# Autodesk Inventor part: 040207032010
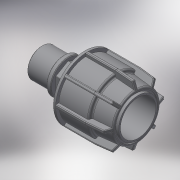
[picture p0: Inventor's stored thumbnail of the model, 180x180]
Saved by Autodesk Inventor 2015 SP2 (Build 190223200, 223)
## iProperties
Created: 2017-08
Part Number: 040207032010
Material: Generic
Description: PLASSON IRRIFIT ADAPTOR 32-1"M
Document SubType Name: Modeling
Designer: KIM
Density: 1 g/cm^3
Appearance: Default
Author: KIM
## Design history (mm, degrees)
derived "040207.ipt"
feature "Solid1::040207.ipt"
tag "TaggingFeature1"
body "Solid1"
other parameters: "d5" = 48, "d6" = 19.14, "d10" = 57, "d22" = 26.441, "d24" = 2.001, "d25" = 51.3, "d26" = 45.6, "d31" = 1.28, "d49" = 2.85, "d50" = 0, "d58" = 0.64, "d61" = 360 deg, "d77" = 32, "d78" = 5 deg, "d80" = 35.2, "d81" = 43.5, "d82" = 2.61, "d84" = 5 deg, "d85" = 70 deg, "d86" = 54.15, "d87" = 0.435, "d88" = 0, "d89" = 48.45, "d90" = 4.35, "d91" = 0, "d99" = 26.441, "d101" = 4, "d102" = 87, "d103" = 31.7292, "d104" = 0.52882, "d108" = 0, "d109" = 0.26441, "d112" = 21.1528, "d113" = 38.4, "d_" = 32, "E_" = 57, "H_" = 87, "l_nut" = 48, "R_" = 26.441
